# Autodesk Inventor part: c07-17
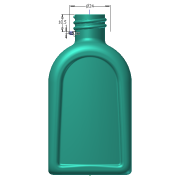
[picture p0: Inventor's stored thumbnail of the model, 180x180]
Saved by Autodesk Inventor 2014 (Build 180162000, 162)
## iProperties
Created: 2010-12
Part Number: c07-17
Material: Generic
Document SubType Name: Modeling
Designer: Beta-8540w
Density: 1 g/cm^3
Appearance: Smooth - Aqua
Author: Beta-8540w
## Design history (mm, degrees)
sketch "Sketch1"
  geometry: L1 (-25, 0)-(25, 0); L2 (25, 0)-(25, 80); L3 (25, 80)-(-25, 80); L4 (-25, 80)-(-25, 0); 2 further points
  constraints: 8 end point, 2 parallel, 1 coincident, 1 horizontal, 1 midpoint, 1 perpendicular
  dimensions: "d0" = 50 distance of L3.end L2.end; "d1" = 80 distance of L2.end L1.end
extrude "Extrusion1" new body sketch "Sketch1" distance "d2" = 15; taper "d3" = 0 deg
feature "FaceDraft1" dims angle "d4" = -2 deg
fillet "Fillet1"
fillet "Fillet2" dims "d5" = 8, "d6" = 8, "d7" = 8, "d8" = 8, "d9" = 8, "d10" = 8, "d11" = 3, "d12" = 3, "d13" = 3, "d14" = 6, "d15" = 5
sketch "Sketch2"
  geometry: L1 (5.522, 12)-(38.474, 12) reference; L2 (0, 0)-(43.996, 0) reference; L3 (41.757, 6.83)-(41.995, 0); L4 (41.925, 2)-(2.071, 2); L5 (2.001, 0)-(2.24, 6.83); L6 (5.522, 10)-(38.474, 10); A1 r 5.284 centre (38.474, 6.716) between (43.755, 6.9) and (38.474, 12) reference; A2 r 5.284 centre (5.522, 6.716) between (5.522, 12) and (0.241, 6.9) reference; A3 r 3.284 centre (38.474, 6.716) between (41.757, 6.83) and (38.474, 10); A4 r 3.284 centre (5.522, 6.716) between (5.522, 10) and (2.24, 6.83); 1 further point
  constraints: 8 end point, 4 point on circle, 4 point on line, 2 centre point, 1 other
  dimensions: "d16" = 2 radial gap between concentric circles of A2 A4
extrude "Extrusion2" cut sketch "Sketch2" distance "d17" = 3; taper "d18" = 0 deg
feature "FaceDraft2" dims angle "d19" = 15 deg
sketch "Sketch3" dims "d20" = 2.5
  geometry: L1 (16.476, 3)-(-16.476, 3) reference; L2 (16.476, 5.5)-(-16.476, 5.5); 9 further points
  constraints: 2 end point, 2 parallel, 1 horizontal alignment, 19 other
extrude "Extrusion3" cut sketch "Sketch3" distance "d21" = 3; taper "d22" = 0 deg
feature "FaceDraft3" dims angle "d23" = 10 deg
workplane "Work Plane1"
sketch "Sketch4"
  geometry: L1 (41.1, -1.222)-(41.476, -12) reference; L2 (41.476, -12)-(-8.524, -12) reference; L3 (-8.524, -12)-(-8.147, -1.222) reference; L4 (-3.776, 3)-(-1.272, 3) reference; L5 (-0.743, 0)-(33.695, 0) reference; L6 (34.225, 3)-(36.728, 3) reference; L7 (-11.024, -1.804)-(43.976, -1.804); A1 r 90 centre (16.476, -87.5) between (43.976, -1.804) and (-11.024, -1.804); 2 further points
  constraints: 2 end point, 2 point on circle, 1 centre point, 1 midpoint, 1 parallel, 1 vertical alignment, 4 other
  dimensions: "d25" = 90 radius of A1; "d26" = 14.5 distance edge to line of A1 L2; "d27" = 55 distance of L7.start L7.end
extrude_surface "ExtrusionSrf1" sketch "Sketch4" dims "d28" = 86, "d29" = 0
feature "Replace Face1"
fillet "Fillet3" dims "d34" = 1, "d35" = 2
mirror "Mirror1"
fillet "Fillet4" dims "d36" = 20
workplane "Work Plane3"
sketch "Sketch6"
  geometry: C1 r 9 at (0, 0); 1 further point
  constraints: 1 centre point, 1 coincident
  dimensions: "d38" = 18 diameter of C1
extrude "Top Boss" join sketch "Sketch6" distance "d39" = 16; taper "d40" = 0 deg
fillet "Fillet5" dims "d41" = 3
shell "Shell1" dims "d62" = 1
sketch "Sketch7"
  geometry: L1 (-9, 80.285)-(-9, 96) reference; C1 r 1 at (-9, 94.5); 1 further point
  constraints: 1 centre point, 1 point on line
  dimensions: "d42" = 1.5 distance of L1.end C1.centre; "d43" = 2 diameter of C1
coil "Coil2" sketch "Sketch7" pitch "d52" = 10; turns "d54" = 2; dims "d53" = 7, "d55" = 0, angle "d56" = 90 deg, angle "d57" = 90 deg, "d58" = 0, "d59" = 0
fillet "Fillet6" dims "d60" = 0.9
fillet "Fillet7" dims "d61" = 0.2
sketch "Sketch8"
  geometry: L1 (-10.5, 85.5)-(-12, 85.5); L2 (-12, 85.5)-(-12, 84.5); L3 (-12, 84.5)-(-10.5, 83.954); L4 (-10.5, 83.954)-(-10.5, 85.5); L5 (0, 0)-(0, 99.062); L6 (-9, 96)-(9, 96) reference; 1 further point
  constraints: 10 end point, 2 parallel, 1 coincident, 1 horizontal, 1 perpendicular
  dimensions: "d63" = 1 distance of L1.end L2.end; "d64" = 20 deg angle of L1 L3; "d65" = 10.5 distance between parallel lines of L6 L1; "d66" = 24 diameter of L2 L5; "d67" = 1.5 distance of L1.start L1.end
fillet "Fillet8"
body "Solid1"
body "Srf1"
node "Project Cut Edges1"
